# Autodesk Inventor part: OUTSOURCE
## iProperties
Shininess: 50.0
Length Units: 11272
Angle Units: 11279
Time Units: 11290
Mass Units: 11286
Length Display Precision: 3
Angle Display Precision: 2
Manager: Cory McConnell
Company: MechaniX Design Solutions
Part Number: OUTSOURCE
Document SubType Name: Modeling
Designer: CM
Material: AISI 1020
Created: 2003-10
Manufacturer: Standard
Standards Organization: Custom
Description: #6 U DRIVE SCREW x 0.3125, SS
Density: 10.49
Volumn: 2.304646865681294
Area: 8.437628188859923
PropertySet Name: Model Information
Control State: 0
Master: False
Checked Out: False
PartAngTol0: 0.5 deg
PartAngTol1: 0.5 deg
PartAngTol2: 0.5 deg
PartAngTol3: 0.5 deg
PartAngTol4: 0.5 deg
PartLinTol1: 0.015 in
PartLinTol2: 0.01 in
PartLinTol3: 0.005 in
PartLinTol4: 0.001 in
Author: CM
Revision Number: 0
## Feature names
1. Revolution5
2. SmallScrew [Revolution]
3. LargeScrew [Revolution]
